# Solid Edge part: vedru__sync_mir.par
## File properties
Author: KULL
Template: Iso Metric Part.par
Last saved by: KULL
Revision: 2
Application: Solid Edge
Accuracy: 0,990
Username: KULL
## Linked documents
vedru__sync.par
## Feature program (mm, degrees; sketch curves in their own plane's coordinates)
part copy "CopiedPart_1"
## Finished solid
Body 1: solid body, 3 faces, 4 edges, 4 vertices.
  Faces by surface: torus 2, spline 1
  Edges by curve: circle 2, intersection 2
Bounding box of the edges (mm; curved faces can reach further): 6.787 x 25.640 x 26.544, from (-6.7872, -79.3784, 14.3974) to (0, -53.7383, 40.9412).
Toroidal faces (ring radius, tube radius in mm): R5.8516 r1.2 x2
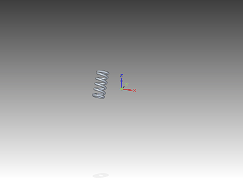
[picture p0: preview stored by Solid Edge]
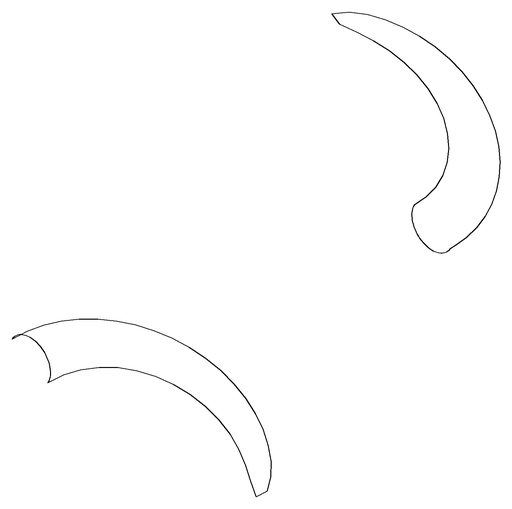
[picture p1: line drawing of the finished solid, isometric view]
